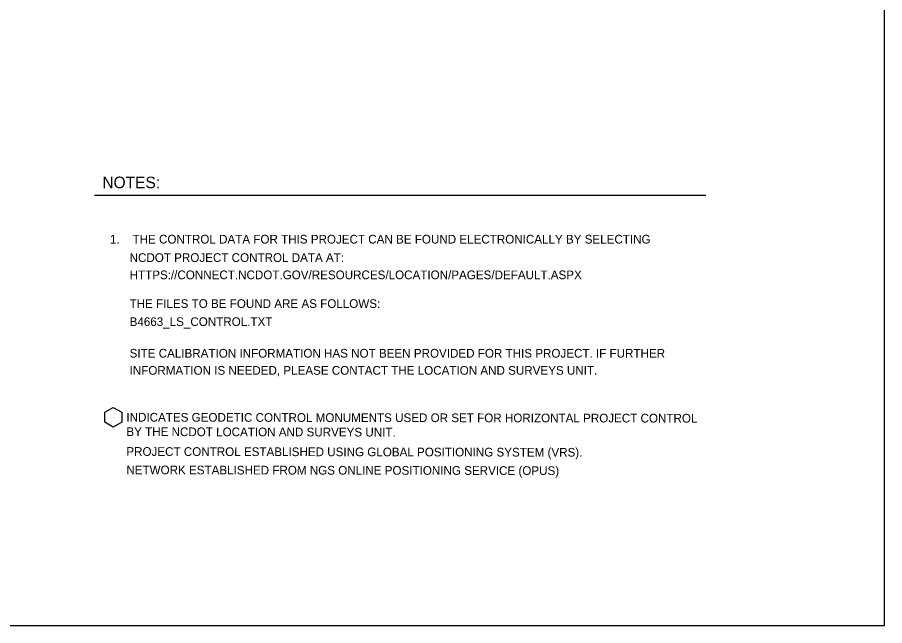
# Model space of a CAD drawing. Extents: x 2169223 to 2172151, y 723262 to 725175.
# Drawn here: x 2171309 to 2172122, y 723306 to 723876 of the extents above; entities that cross this region are included whole.
import ezdxf

# ---------------------------------------------------------------- set-up
doc = ezdxf.new("R2010")
doc.units = 0
for name, color, linetype in [('CTL GPS Horizontal CELL', 7, 'Continuous'), ('CTL Sheet Border CELL', 7, 'Continuous'), ('CTL Sheet Notes CELL', 7, 'Continuous')]:
    doc.layers.add(name, color=color, linetype=linetype)

# ---------------------------------------------------------------- blocks, each defined once
blk = doc.blocks.new('CTL GPS HORIZONTAL')
at = {"layer": 'CTL GPS Horizontal CELL'}
blk.add_line((0, 0), (0, 0), dxfattribs=at)
blk.add_lwpolyline([(0, -0.07375), (-0.06425, -0.03725), (-0.06425, 0.0365), (0, 0.07375), (0.06425, 0.03725), (0.06425, -0.03725), (0, -0.07375)], dxfattribs=at)

msp = doc.modelspace()

# ---------------------------------------------------------------- linework, layer by layer
at = {"layer": 'CTL Sheet Border CELL'}
msp.add_lwpolyline([(2172121.89, 725131.92), (2169513.19, 725131.84), (2169513.25, 723305.76), (2172121.95, 723305.85)], close=True, dxfattribs=at)
at = {"layer": 'CTL Sheet Notes CELL'}
msp.add_line((2171380.98, 723709.19), (2171954.29, 723709.19), dxfattribs=at)

# ---------------------------------------------------------------- block references
at = {"layer": 'CTL GPS Horizontal CELL', "xscale": 125, "yscale": 125}
msp.add_blockref('CTL GPS HORIZONTAL', (2171398.58, 723501.08), dxfattribs=at)

# ---------------------------------------------------------------- texts
at = {"layer": 'CTL Sheet Notes CELL'}
for s, height, p in [('NOTES:', 10.87, (2171388.39, 723715.67)), ('INDICATES GEODETIC CONTROL MONUMENTS USED OR SET FOR HORIZONTAL PROJECT CONTROL', 8.1522, (2171410.93, 723497)), ('BY THE NCDOT LOCATION AND SURVEYS UNIT.', 8.1522, (2171410.87, 723483.42)), ('PROJECT CONTROL ESTABLISHED USING GLOBAL POSITIONING SYSTEM (VRS).', 8.1522, (2171410.87, 723464.89)), ('NETWORK ESTABLISHED FROM NGS ONLINE POSITIONING SERVICE (OPUS)', 8.1522, (2171410.87, 723447.64))]:
    msp.add_text(s, height=height, rotation=359.89475, dxfattribs=at).set_placement(p)
for s, p in [('1.    THE CONTROL DATA FOR THIS PROJECT CAN BE FOUND ELECTRONICALLY BY SELECTING', (2171395.47, 723663.79)), ('NCDOT PROJECT CONTROL DATA AT:', (2171413.94, 723646.55)), ('HTTPS://CONNECT.NCDOT.GOV/RESOURCES/LOCATION/PAGES/DEFAULT.ASPX', (2171413.94, 723630.38)), ('THE FILES TO BE FOUND ARE AS FOLLOWS:', (2171413.94, 723603.44)), ('B4663_LS_CONTROL.TXT', (2171413.94, 723586.51)), ('SITE CALIBRATION INFORMATION HAS NOT BEEN PROVIDED FOR THIS PROJECT. IF FURTHER', (2171413.94, 723556.92)), ('INFORMATION IS NEEDED, PLEASE CONTACT THE LOCATION AND SURVEYS UNIT.', (2171413.94, 723540.87))]:
    msp.add_text(s, height=8.1522, dxfattribs=at).set_placement(p)

doc.saveas('drawing.dxf')
